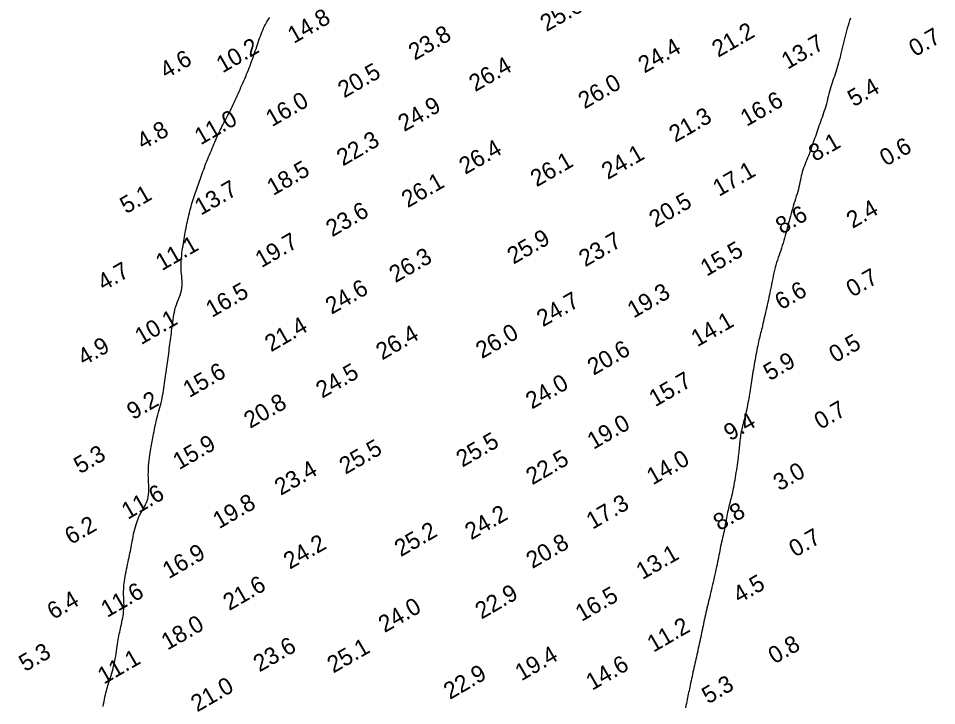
# Model space of a CAD drawing. Extents: x 3024098 to 3056816, y 418252 to 509144.
# Drawn here: x 3026992.4 to 3027264.4, y 423526.8 to 423730.5 of the extents above; entities that cross this region are included whole.
import ezdxf

# ---------------------------------------------------------------- set-up
doc = ezdxf.new("R2010")
doc.units = 0
doc.layers.add('V-CHAN-CONT-EL10', color=7, linetype='Continuous')
doc.layers.add('V-TOPO-SOUN-0911', color=7, linetype='Continuous')

msp = doc.modelspace()

# ---------------------------------------------------------------- linework, layer by layer
at = {"layer": 'V-CHAN-CONT-EL10'}
for points in [[(3027017.45, 423526.6), (3027017.61, 423527.32), (3027017.75, 423528.02), (3027017.88, 423528.71), (3027018.01, 423529.37), (3027018.14, 423530.01), (3027018.28, 423530.61), (3027018.43, 423531.18), (3027018.58, 423531.74), (3027018.74, 423532.28), (3027018.91, 423532.82), (3027019.08, 423533.37), (3027019.26, 423533.93), (3027019.44, 423534.51), (3027019.63, 423535.11), (3027019.83, 423535.75), (3027020.02, 423536.41), (3027020.21, 423537.09), (3027020.4, 423537.79), (3027020.58, 423538.5), (3027020.75, 423539.23), (3027020.91, 423539.98), (3027021.06, 423540.73), (3027021.19, 423541.48), (3027021.31, 423542.23), (3027021.43, 423542.97), (3027021.53, 423543.7), (3027021.64, 423544.41), (3027021.74, 423545.1), (3027021.84, 423545.75), (3027021.95, 423546.36), (3027022.05, 423546.95), (3027022.16, 423547.52), (3027022.27, 423548.07), (3027022.39, 423548.61), (3027022.51, 423549.16), (3027022.63, 423549.72), (3027022.76, 423550.3), (3027022.89, 423550.91), (3027023.02, 423551.53), (3027023.15, 423552.17), (3027023.27, 423552.82), (3027023.39, 423553.48), (3027023.48, 423554.13), (3027023.56, 423554.78), (3027023.62, 423555.42), (3027023.65, 423556.04), (3027023.66, 423556.65), (3027023.65, 423557.25), (3027023.64, 423557.84), (3027023.61, 423558.42), (3027023.59, 423559), (3027023.56, 423559.57), (3027023.55, 423560.14), (3027023.56, 423560.72), (3027023.57, 423561.3), (3027023.6, 423561.9), (3027023.65, 423562.5), (3027023.71, 423563.11), (3027023.79, 423563.75), (3027023.88, 423564.4), (3027023.99, 423565.08), (3027024.12, 423565.77), (3027024.26, 423566.49), (3027024.41, 423567.22), (3027024.57, 423567.95), (3027024.72, 423568.67), (3027024.88, 423569.39), (3027025.03, 423570.08), (3027025.17, 423570.74), (3027025.3, 423571.37), (3027025.43, 423571.98), (3027025.54, 423572.57), (3027025.65, 423573.15), (3027025.76, 423573.73), (3027025.87, 423574.33), (3027025.98, 423574.94), (3027026.1, 423575.59), (3027026.23, 423576.27), (3027026.37, 423576.97), (3027026.52, 423577.7), (3027026.68, 423578.42), (3027026.85, 423579.14), (3027027.03, 423579.84), (3027027.22, 423580.51), (3027027.42, 423581.13), (3027027.62, 423581.7), (3027027.83, 423582.23), (3027028.05, 423582.73), (3027028.28, 423583.19), (3027028.52, 423583.64), (3027028.76, 423584.08), (3027029.01, 423584.53), (3027029.27, 423584.98), (3027029.53, 423585.46), (3027029.79, 423585.95), (3027030.05, 423586.46), (3027030.29, 423587), (3027030.5, 423587.56), (3027030.69, 423588.14), (3027030.84, 423588.75), (3027030.95, 423589.38), (3027031.01, 423590.04), (3027031.03, 423590.72), (3027031.02, 423591.43), (3027030.99, 423592.16), (3027030.95, 423592.91), (3027030.91, 423593.69), (3027030.88, 423594.49), (3027030.86, 423595.31), (3027030.87, 423596.15), (3027030.9, 423597), (3027030.96, 423597.86), (3027031.03, 423598.7), (3027031.11, 423599.53), (3027031.2, 423600.32), (3027031.3, 423601.07), (3027031.4, 423601.76), (3027031.5, 423602.4), (3027031.59, 423602.98), (3027031.69, 423603.53), (3027031.78, 423604.05), (3027031.88, 423604.57), (3027031.98, 423605.08), (3027032.08, 423605.61), (3027032.19, 423606.17), (3027032.31, 423606.77), (3027032.43, 423607.4), (3027032.56, 423608.06), (3027032.69, 423608.75), (3027032.84, 423609.45), (3027032.99, 423610.17), (3027033.16, 423610.89), (3027033.33, 423611.61), (3027033.51, 423612.33), (3027033.71, 423613.04), (3027033.9, 423613.76), (3027034.09, 423614.47), (3027034.29, 423615.18), (3027034.47, 423615.89), (3027034.65, 423616.6), (3027034.82, 423617.32), (3027034.97, 423618.04), (3027035.11, 423618.76), (3027035.23, 423619.48), (3027035.35, 423620.21), (3027035.46, 423620.93), (3027035.56, 423621.64), (3027035.67, 423622.35), (3027035.77, 423623.05), (3027035.87, 423623.75), (3027035.97, 423624.43), (3027036.07, 423625.11), (3027036.17, 423625.78), (3027036.27, 423626.45), (3027036.37, 423627.12), (3027036.46, 423627.79), (3027036.56, 423628.47), (3027036.65, 423629.15), (3027036.74, 423629.83), (3027036.83, 423630.52), (3027036.92, 423631.21), (3027037.01, 423631.89), (3027037.09, 423632.57), (3027037.18, 423633.25), (3027037.26, 423633.92), (3027037.35, 423634.59), (3027037.43, 423635.25), (3027037.52, 423635.91), (3027037.6, 423636.57), (3027037.69, 423637.23), (3027037.77, 423637.89), (3027037.86, 423638.56), (3027037.94, 423639.23), (3027038.02, 423639.92), (3027038.11, 423640.61), (3027038.2, 423641.31), (3027038.31, 423642.02), (3027038.43, 423642.73), (3027038.58, 423643.45), (3027038.75, 423644.17), (3027038.96, 423644.88), (3027039.2, 423645.6), (3027039.46, 423646.32), (3027039.73, 423647.03), (3027040, 423647.75), (3027040.26, 423648.46), (3027040.49, 423649.17), (3027040.68, 423649.88), (3027040.81, 423650.59), (3027040.88, 423651.29), (3027040.9, 423651.99), (3027040.88, 423652.69), (3027040.82, 423653.4), (3027040.75, 423654.12), (3027040.68, 423654.84), (3027040.61, 423655.57), (3027040.57, 423656.32), (3027040.55, 423657.08), (3027040.57, 423657.85), (3027040.61, 423658.63), (3027040.67, 423659.41), (3027040.75, 423660.18), (3027040.83, 423660.94), (3027040.93, 423661.69), (3027041.03, 423662.42), (3027041.14, 423663.13), (3027041.24, 423663.82), (3027041.34, 423664.48), (3027041.45, 423665.14), (3027041.56, 423665.79), (3027041.67, 423666.43), (3027041.78, 423667.06), (3027041.9, 423667.7), (3027042.03, 423668.34), (3027042.16, 423668.99), (3027042.3, 423669.64), (3027042.44, 423670.29), (3027042.59, 423670.93), (3027042.74, 423671.58), (3027042.89, 423672.22), (3027043.04, 423672.86), (3027043.2, 423673.5), (3027043.35, 423674.12), (3027043.52, 423674.75), (3027043.68, 423675.36), (3027043.85, 423675.97), (3027044.03, 423676.57), (3027044.21, 423677.16), (3027044.4, 423677.74), (3027044.6, 423678.32), (3027044.8, 423678.88), (3027045.01, 423679.44), (3027045.22, 423680), (3027045.43, 423680.55), (3027045.64, 423681.11), (3027045.85, 423681.66), (3027046.05, 423682.23), (3027046.25, 423682.8), (3027046.45, 423683.37), (3027046.65, 423683.96), (3027046.85, 423684.54), (3027047.06, 423685.14), (3027047.27, 423685.74), (3027047.48, 423686.35), (3027047.71, 423686.97), (3027047.95, 423687.59), (3027048.2, 423688.22), (3027048.46, 423688.85), (3027048.73, 423689.48), (3027049, 423690.12), (3027049.27, 423690.75), (3027049.54, 423691.39), (3027049.8, 423692.02), (3027050.06, 423692.64), (3027050.32, 423693.26), (3027050.57, 423693.88), (3027050.83, 423694.48), (3027051.08, 423695.09), (3027051.33, 423695.67), (3027051.59, 423696.25), (3027051.86, 423696.82), (3027052.13, 423697.38), (3027052.4, 423697.92), (3027052.69, 423698.47), (3027052.97, 423699.01), (3027053.27, 423699.55), (3027053.56, 423700.1), (3027053.86, 423700.67), (3027054.16, 423701.24), (3027054.46, 423701.84), (3027054.77, 423702.45), (3027055.07, 423703.07), (3027055.38, 423703.71), (3027055.68, 423704.35), (3027055.98, 423704.99), (3027056.29, 423705.64), (3027056.58, 423706.29), (3027056.88, 423706.92), (3027057.17, 423707.56), (3027057.46, 423708.2), (3027057.75, 423708.83), (3027058.04, 423709.46), (3027058.32, 423710.09), (3027058.6, 423710.73), (3027058.88, 423711.37), (3027059.16, 423712.01), (3027059.44, 423712.65), (3027059.71, 423713.3), (3027059.99, 423713.95), (3027060.25, 423714.59), (3027060.51, 423715.24), (3027060.77, 423715.88), (3027061.01, 423716.51), (3027061.25, 423717.15), (3027061.48, 423717.77), (3027061.7, 423718.4), (3027061.92, 423719.02), (3027062.13, 423719.64), (3027062.35, 423720.26), (3027062.56, 423720.89), (3027062.77, 423721.51), (3027062.98, 423722.15), (3027063.19, 423722.78), (3027063.4, 423723.41), (3027063.62, 423724.04), (3027063.84, 423724.67), (3027064.06, 423725.29), (3027064.29, 423725.89), (3027064.53, 423726.49), (3027064.77, 423727.07), (3027065.01, 423727.64), (3027065.27, 423728.19), (3027065.54, 423728.73), (3027065.83, 423729.26), (3027066.14, 423729.77), (3027066.48, 423730.28), (3027066.83, 423730.78)], [(3027238.88, 423730.58), (3027238.65, 423729.86), (3027238.42, 423729.14), (3027238.19, 423728.4), (3027237.97, 423727.64), (3027237.76, 423726.87), (3027237.55, 423726.09), (3027237.35, 423725.3), (3027237.15, 423724.5), (3027236.96, 423723.69), (3027236.77, 423722.89), (3027236.58, 423722.08), (3027236.38, 423721.27), (3027236.19, 423720.47), (3027235.99, 423719.68), (3027235.8, 423718.9), (3027235.6, 423718.13), (3027235.39, 423717.38), (3027235.19, 423716.64), (3027234.98, 423715.93), (3027234.77, 423715.25), (3027234.55, 423714.59), (3027234.33, 423713.95), (3027234.12, 423713.32), (3027233.9, 423712.71), (3027233.69, 423712.09), (3027233.48, 423711.47), (3027233.27, 423710.84), (3027233.07, 423710.19), (3027232.88, 423709.52), (3027232.69, 423708.83), (3027232.51, 423708.12), (3027232.33, 423707.4), (3027232.14, 423706.68), (3027231.96, 423705.96), (3027231.77, 423705.24), (3027231.57, 423704.54), (3027231.36, 423703.84), (3027231.15, 423703.16), (3027230.93, 423702.49), (3027230.7, 423701.83), (3027230.47, 423701.18), (3027230.24, 423700.54), (3027230.01, 423699.9), (3027229.78, 423699.26), (3027229.56, 423698.63), (3027229.34, 423698), (3027229.12, 423697.38), (3027228.9, 423696.75), (3027228.69, 423696.14), (3027228.49, 423695.53), (3027228.28, 423694.92), (3027228.08, 423694.33), (3027227.88, 423693.74), (3027227.69, 423693.16), (3027227.49, 423692.58), (3027227.29, 423692.01), (3027227.08, 423691.44), (3027226.88, 423690.88), (3027226.66, 423690.31), (3027226.44, 423689.74), (3027226.2, 423689.17), (3027225.96, 423688.6), (3027225.72, 423688.03), (3027225.48, 423687.45), (3027225.24, 423686.86), (3027225.02, 423686.27), (3027224.81, 423685.68), (3027224.63, 423685.08), (3027224.46, 423684.47), (3027224.32, 423683.86), (3027224.18, 423683.23), (3027224.06, 423682.6), (3027223.93, 423681.96), (3027223.79, 423681.3), (3027223.65, 423680.63), (3027223.48, 423679.95), (3027223.29, 423679.24), (3027223.08, 423678.53), (3027222.86, 423677.8), (3027222.63, 423677.07), (3027222.39, 423676.34), (3027222.15, 423675.6), (3027221.92, 423674.86), (3027221.69, 423674.12), (3027221.48, 423673.39), (3027221.29, 423672.67), (3027221.1, 423671.94), (3027220.91, 423671.22), (3027220.73, 423670.5), (3027220.55, 423669.78), (3027220.37, 423669.06), (3027220.18, 423668.33), (3027219.99, 423667.6), (3027219.79, 423666.86), (3027219.58, 423666.12), (3027219.37, 423665.38), (3027219.15, 423664.64), (3027218.92, 423663.91), (3027218.69, 423663.18), (3027218.46, 423662.45), (3027218.22, 423661.74), (3027217.98, 423661.02), (3027217.73, 423660.31), (3027217.49, 423659.6), (3027217.26, 423658.88), (3027217.03, 423658.15), (3027216.81, 423657.4), (3027216.6, 423656.64), (3027216.4, 423655.86), (3027216.21, 423655.06), (3027216.03, 423654.25), (3027215.86, 423653.43), (3027215.69, 423652.61), (3027215.53, 423651.79), (3027215.37, 423650.98), (3027215.21, 423650.18), (3027215.05, 423649.39), (3027214.89, 423648.62), (3027214.73, 423647.87), (3027214.57, 423647.12), (3027214.4, 423646.38), (3027214.24, 423645.65), (3027214.08, 423644.93), (3027213.92, 423644.2), (3027213.76, 423643.48), (3027213.6, 423642.76), (3027213.44, 423642.06), (3027213.28, 423641.36), (3027213.13, 423640.69), (3027212.98, 423640.04), (3027212.83, 423639.41), (3027212.69, 423638.82), (3027212.55, 423638.27), (3027212.42, 423637.74), (3027212.29, 423637.23), (3027212.16, 423636.73), (3027212.04, 423636.23), (3027211.91, 423635.73), (3027211.79, 423635.21), (3027211.66, 423634.66), (3027211.54, 423634.08), (3027211.41, 423633.47), (3027211.28, 423632.83), (3027211.15, 423632.17), (3027211.02, 423631.49), (3027210.89, 423630.79), (3027210.76, 423630.08), (3027210.63, 423629.36), (3027210.51, 423628.64), (3027210.38, 423627.92), (3027210.26, 423627.2), (3027210.14, 423626.47), (3027210.02, 423625.76), (3027209.9, 423625.05), (3027209.79, 423624.35), (3027209.69, 423623.66), (3027209.58, 423622.99), (3027209.48, 423622.33), (3027209.38, 423621.68), (3027209.29, 423621.04), (3027209.19, 423620.4), (3027209.09, 423619.77), (3027208.99, 423619.14), (3027208.89, 423618.5), (3027208.78, 423617.87), (3027208.66, 423617.23), (3027208.54, 423616.59), (3027208.42, 423615.95), (3027208.29, 423615.31), (3027208.16, 423614.67), (3027208.02, 423614.04), (3027207.87, 423613.41), (3027207.71, 423612.79), (3027207.56, 423612.17), (3027207.4, 423611.55), (3027207.24, 423610.95), (3027207.08, 423610.35), (3027206.94, 423609.77), (3027206.8, 423609.19), (3027206.67, 423608.62), (3027206.56, 423608.07), (3027206.45, 423607.53), (3027206.36, 423606.99), (3027206.28, 423606.47), (3027206.21, 423605.95), (3027206.15, 423605.45), (3027206.09, 423604.95), (3027206.04, 423604.45), (3027205.98, 423603.96), (3027205.94, 423603.46), (3027205.89, 423602.97), (3027205.84, 423602.46), (3027205.78, 423601.93), (3027205.73, 423601.38), (3027205.66, 423600.8), (3027205.59, 423600.19), (3027205.5, 423599.55), (3027205.41, 423598.87), (3027205.31, 423598.16), (3027205.21, 423597.43), (3027205.09, 423596.69), (3027204.98, 423595.94), (3027204.85, 423595.18), (3027204.73, 423594.42), (3027204.6, 423593.67), (3027204.47, 423592.94), (3027204.34, 423592.21), (3027204.21, 423591.5), (3027204.07, 423590.82), (3027203.94, 423590.15), (3027203.8, 423589.52), (3027203.67, 423588.92), (3027203.53, 423588.35), (3027203.4, 423587.81), (3027203.26, 423587.29), (3027203.13, 423586.78), (3027203, 423586.27), (3027202.87, 423585.77), (3027202.75, 423585.25), (3027202.63, 423584.72), (3027202.51, 423584.16), (3027202.4, 423583.58), (3027202.29, 423582.98), (3027202.17, 423582.37), (3027202.06, 423581.74), (3027201.94, 423581.1), (3027201.82, 423580.46), (3027201.7, 423579.82), (3027201.56, 423579.17), (3027201.43, 423578.53), (3027201.28, 423577.88), (3027201.14, 423577.24), (3027200.99, 423576.6), (3027200.85, 423575.96), (3027200.71, 423575.32), (3027200.57, 423574.68), (3027200.44, 423574.04), (3027200.31, 423573.4), (3027200.18, 423572.76), (3027200.06, 423572.11), (3027199.93, 423571.46), (3027199.8, 423570.79), (3027199.67, 423570.1), (3027199.52, 423569.41), (3027199.38, 423568.69), (3027199.22, 423567.96), (3027199.05, 423567.21), (3027198.89, 423566.46), (3027198.71, 423565.7), (3027198.54, 423564.94), (3027198.37, 423564.18), (3027198.19, 423563.43), (3027198.02, 423562.69), (3027197.85, 423561.96), (3027197.68, 423561.23), (3027197.52, 423560.51), (3027197.35, 423559.8), (3027197.19, 423559.1), (3027197.02, 423558.41), (3027196.86, 423557.73), (3027196.7, 423557.05), (3027196.54, 423556.38), (3027196.38, 423555.71), (3027196.22, 423555.05), (3027196.07, 423554.39), (3027195.92, 423553.74), (3027195.77, 423553.08), (3027195.62, 423552.42), (3027195.48, 423551.76), (3027195.34, 423551.1), (3027195.21, 423550.43), (3027195.07, 423549.77), (3027194.94, 423549.1), (3027194.8, 423548.44), (3027194.67, 423547.78), (3027194.53, 423547.12), (3027194.39, 423546.47), (3027194.25, 423545.82), (3027194.11, 423545.17), (3027193.96, 423544.52), (3027193.82, 423543.87), (3027193.68, 423543.22), (3027193.53, 423542.57), (3027193.38, 423541.92), (3027193.24, 423541.27), (3027193.1, 423540.62), (3027192.95, 423539.97), (3027192.81, 423539.31), (3027192.66, 423538.66), (3027192.52, 423538), (3027192.38, 423537.35), (3027192.24, 423536.7), (3027192.1, 423536.04), (3027191.96, 423535.4), (3027191.82, 423534.76), (3027191.68, 423534.13), (3027191.55, 423533.51), (3027191.42, 423532.91), (3027191.3, 423532.33), (3027191.18, 423531.77), (3027191.07, 423531.23), (3027190.96, 423530.71), (3027190.86, 423530.19), (3027190.75, 423529.68), (3027190.64, 423529.15), (3027190.53, 423528.61), (3027190.41, 423528.05), (3027190.29, 423527.45), (3027190.15, 423526.82), (3027190, 423526.15)]]:
    msp.add_lwpolyline(points, dxfattribs=at)

# ---------------------------------------------------------------- texts
at = {"layer": 'V-TOPO-SOUN-0911'}
for s, p in [('25.6 ', (3027148.82, 423726.45)), ('14.8 ', (3027073.98, 423722.93)), ('23.8 ', (3027109.78, 423717.94)), ('21.2 ', (3027199.7, 423718.83)), ('0.7', (3027258.04, 423719.03)), ('13.7 ', (3027220.28, 423715.29)), ('10.2 ', (3027052.85, 423714.2)), ('24.4 ', (3027177.85, 423714.14)), ('4.6', (3027036.15, 423712.51)), ('20.5 ', (3027088.87, 423706.79)), ('26.4 ', (3027127.72, 423708.66)), ('26.0 ', (3027160.09, 423703.54)), ('5.4', (3027239.89, 423704.17)), ('16.0 ', (3027067.5, 423698.26)), ('16.6 ', (3027208.14, 423698.36)), ('24.9 ', (3027106.69, 423696.82)), ('11.0 ', (3027046.38, 423692.88)), ('21.3 ', (3027186.98, 423693.63)), ('4.8', (3027029.3, 423691.47)), ('22.3 ', (3027088.52, 423686.61)), ('8.1', (3027228.36, 423687.95)), ('0.6', (3027249.41, 423686.56)), ('26.4 ', (3027124.77, 423684.12)), ('24.1 ', (3027167.01, 423682.62)), ('26.1 ', (3027145.91, 423680.43)), ('18.5 ', (3027067.84, 423677.85)), ('17.1 ', (3027199.95, 423677.6)), ('26.1 ', (3027107.73, 423674.26)), ('13.7 ', (3027046.42, 423672.01)), ('5.1', (3027024.29, 423672.46)), ('20.5 ', (3027181.06, 423668.4)), ('23.6 ', (3027085.33, 423665.62)), ('2.4', (3027239.53, 423668.11)), ('8.6', (3027218.57, 423666.41)), ('25.9 ', (3027139.04, 423657.51)), ('11.1 ', (3027034.89, 423655.59)), ('19.7 ', (3027064.37, 423656.46)), ('23.7 ', (3027160.27, 423656.72)), ('26.3 ', (3027104.07, 423652.03)), ('15.5 ', (3027196.28, 423653.93)), ('4.7', (3027017.65, 423649.64)), ('0.7', (3027239.47, 423647.74)), ('16.5 ', (3027049.73, 423641.73)), ('24.6 ', (3027085.17, 423642.65)), ('19.3 ', (3027174.64, 423641.53)), ('6.6', (3027218.34, 423643.94)), ('24.7 ', (3027147.77, 423638.94)), ('10.1 ', (3027028.72, 423633.64)), ('21.4 ', (3027067.22, 423631.53)), ('14.1 ', (3027193.52, 423633.02)), ('26.4 ', (3027100.16, 423629.13)), ('26.0 ', (3027129.71, 423629.52)), ('4.9', (3027011.78, 423627.43)), ('20.6 ', (3027162.79, 423624.58)), ('0.5', (3027234.37, 423628.32)), ('5.9', (3027214.96, 423622.97)), ('15.6 ', (3027042.98, 423617.95)), ('24.5 ', (3027082.37, 423617.78)), ('24.0 ', (3027144.51, 423614.56)), ('15.7 ', (3027181.04, 423615.25)), ('9.2', (3027026.34, 423611.42)), ('20.8 ', (3027061.02, 423608.82)), ('0.7', (3027229.99, 423608.53)), ('9.4', (3027203.21, 423605.12)), ('19.0 ', (3027162.75, 423602.62)), ('25.5 ', (3027123.91, 423597.34)), ('15.9 ', (3027039.99, 423596.59)), ('25.5 ', (3027089.29, 423595.24)), ('5.3', (3027010.63, 423595.38)), ('22.5 ', (3027144.61, 423592.12)), ('14.0 ', (3027180.36, 423592.09)), ('23.4 ', (3027070.11, 423588.97)), ('3.0', (3027217.86, 423590.29)), ('11.6 ', (3027024.77, 423581.86)), ('19.8 ', (3027051.84, 423579.1)), ('17.3 ', (3027162.47, 423578.93)), ('24.2 ', (3027126.51, 423575.79)), ('8.8', (3027200.1, 423578.48)), ('6.2', (3027007.94, 423574.41)), ('25.2 ', (3027105.64, 423570.8)), ('0.7', (3027222.51, 423570.67)), ('24.2 ', (3027072.77, 423567.09)), ('20.8 ', (3027144.65, 423567.29)), ('16.9 ', (3027036.91, 423564.27)), ('13.1 ', (3027177.25, 423564.02)), ('21.6 ', (3027054.85, 423554.83)), ('4.5', (3027205.96, 423557.03)), ('11.6 ', (3027018.67, 423552.79)), ('22.9 ', (3027129.56, 423552.29)), ('16.5 ', (3027159.24, 423551.61)), ('6.4', (3027002.72, 423552.19)), ('24.0 ', (3027100.87, 423548.29)), ('18.0 ', (3027036.53, 423543.11)), ('11.2 ', (3027180.51, 423542.48)), ('23.6 ', (3027063.81, 423536.65)), ('25.1 ', (3027085.68, 423536.3)), ('0.8', (3027216.37, 423539.01)), ('5.3', (3026994.38, 423536.74)), ('11.1 ', (3027017.7, 423533.02)), ('19.4 ', (3027141.37, 423533.99)), ('14.6 ', (3027162.37, 423531.2)), ('22.9 ', (3027120.21, 423528.48)), ('21.0 ', (3027045.33, 423524.77)), ('5.3', (3027196.72, 423527.17))]:
    msp.add_text(s, height=5, rotation=30, dxfattribs=at).set_placement(p)

doc.saveas('drawing.dxf')
